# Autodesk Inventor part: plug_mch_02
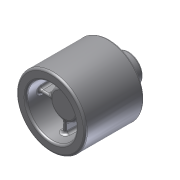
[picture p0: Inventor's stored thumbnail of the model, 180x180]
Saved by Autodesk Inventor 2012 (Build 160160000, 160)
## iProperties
Shininess: 64.0
Length Units: 11269
Angle Units: 11279
Time Units: 11290
Mass Units: 11283
Length Display Precision: 3
Angle Display Precision: 2
Company: Autodesk
Created: 2002-07
Part Number: plug_mch_02
Document SubType Name: Modeling
Designer: Lieven Grauls
Stock Number: plug_mch_02
Project: Valve Techcamp 2008
Density: 1 g/cm^3
Material: Default
Density: 0.0
Volumn: 0.0
Area: 0.0
PropertySet Name: Model Information
Control State: 0
Master: False
Checked Out: False
Author: Lieven Grauls
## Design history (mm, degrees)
node "plug_cast_02" dims "d1" = 10
sketch "Sketch6"
  geometry: L1 (-25, 35)-(25, 35) reference; L2 (26.5, 33.5)-(26.5, 0) reference; L3 (25, 35)-(26.5, 35); L4 (26.5, 35)-(26.5, 33.5); L5 (25, 35)-(26.5, 33.5); L6 (0, -7)-(0, 42) reference; 1 further point
  constraints: 6 end point, 2 perpendicular
revolve "Revolution2" sketch "Sketch6" stored, may be unused: angle "d47" = 90 deg
node "Volumenkörper1"
node "Volumenkörpern"
node "Oberflächenkörpern"
tag "Bezeichnung2"
feature "Volumenkörper1::plug_cast_02" dims "d1" = 10
other parameters: "d2" = 50.65
